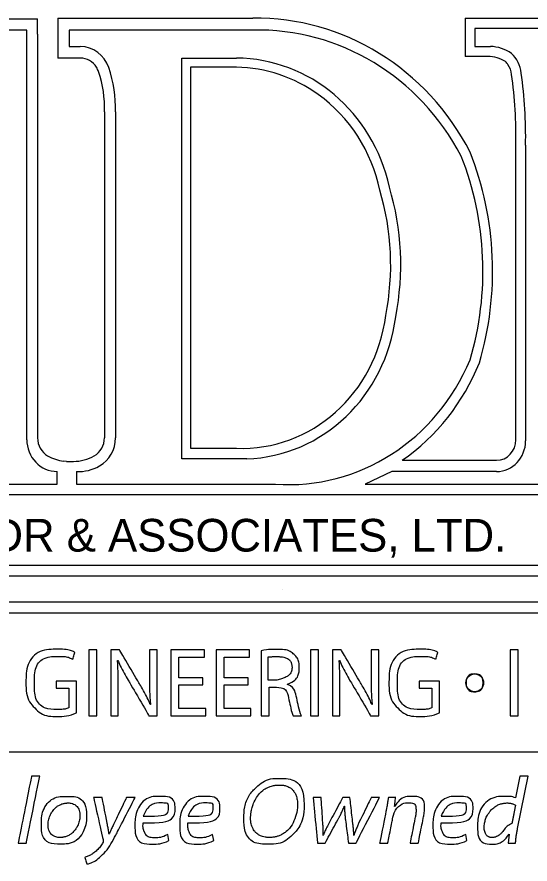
# Model space of a CAD drawing. Extents: x 0 to 170, y 0 to 110.
# Drawn here: x 162.45 to 164.962, y 16.154 to 20.302 of the extents above; entities that cross this region are included whole.
import ezdxf

# ---------------------------------------------------------------- set-up
doc = ezdxf.new("R2010")
doc.units = 0
doc.layers.add('SH_Data', color=7, linetype='Continuous')

msp = doc.modelspace()

# ---------------------------------------------------------------- linework, layer by layer
at = {"layer": 'SH_Data'}
for p, q in [((162.1704, 20.2922), (162.5504, 20.2922)), ((162.5504, 20.2173), (162.5504, 20.2922)), ((162.6498, 20.295), (162.6498, 20.1001)), ((162.6498, 20.295), (163.6048, 20.295)), ((164.6448, 20.295), (164.6448, 20.1073)), ((164.6448, 20.295), (165.5998, 20.295)), ((164.6448, 20.295), (164.6448, 20.1073)), ((164.6448, 20.295), (165.5998, 20.295)), ((162.5504, 20.2173), (162.5504, 18.2406)), ((162.721, 20.1001), (162.6498, 20.1001)), ((162.7599, 20.1001), (162.721, 20.1001)), ((164.716, 20.1073), (164.6448, 20.1073)), ((164.716, 20.1073), (164.6448, 20.1073)), ((164.7549, 20.1073), (164.716, 20.1073)), ((163.5243, 20.0551), (163.2988, 20.0551)), ((163.2988, 20.0551), (163.2988, 18.1896)), ((162.8783, 19.8365), (162.8783, 18.2406)), ((164.8926, 18.231), (164.8926, 19.6737)), ((163.2988, 18.1896), (163.3416, 18.1896)), ((163.3416, 18.1896), (163.5243, 18.1896)), ((162.6919, 18.1258), (162.6779, 18.1271)), ((162.6919, 18.1258), (162.6779, 18.1271)), ((162.6919, 18.1258), (162.7267, 18.1258)), ((164.3366, 18.131), (164.7976, 18.131)), ((161.0559, 17.6168), (166.4337, 17.6168)), ((163.75, 17.5), (163.75, 17.5)), ((167.2019, 17.3832), (160.3503, 17.3832)), ((163.7835, 17.1535), (163.7838, 17.1532)), ((163.6845, 17.0548), (163.6804, 17.0548)), ((163.7396, 17.0597), (163.7227, 17.0547)), ((163.7627, 17.068), (163.7396, 17.0597)), ((163.7746, 17.0336), (163.7746, 17.0351)), ((163.802, 16.88), (163.8424, 16.88)), ((160.2778, 16.7035), (167.2019, 16.7035)), ((163.6458, 16.5077), (163.6458, 16.5077)), ((164.8779, 16.4481), (164.8908, 16.4423)), ((163.1939, 16.2696), (163.1881, 16.2983)), ((163.4131, 16.2696), (163.4073, 16.2983)), ((164.6529, 16.2696), (164.647, 16.2983))]:
    msp.add_line(p, q, dxfattribs=at)
for points in [[(165.5998, 20.245), (164.6923, 20.245), (164.6923, 20.1573), (164.7678, 20.1573)], [(162.4982, 18.2317), (162.4982, 20.2372), (162.1988, 20.2372), (160.6706, 17.7601)], [(163.6048, 20.2372), (162.7049, 20.2372), (162.7049, 20.1566), (162.7599, 20.1566)], [(163.2569, 18.1379), (163.2569, 20.1001), (163.5243, 20.1001)], [(162.932, 19.8365), (162.932, 19.8341), (162.932, 18.2406)], [(164.9401, 19.6732), (164.9401, 18.226)], [(165.4659, 18.986), (166.5374, 17.5632), (161.0191, 17.5632)], [(163.5751, 18.1379), (163.2569, 18.1379)], [(164.3366, 18.131), (164.4469, 18.131)], [(162.0588, 18.0762), (161.2755, 18.0762), (161.2381, 18.0137), (162.646, 18.0137), (162.646, 18.0762)], [(162.7418, 18.0762), (162.7418, 18.0137), (163.7158, 18.0137)], [(164.7976, 18.076), (164.2849, 18.076), (164.1554, 18.0137), (166.1084, 18.0137), (166.0617, 18.076), (165.4111, 18.076)], [(166.2128, 17.9112), (166.1753, 17.9612), (161.2059, 17.9612), (161.0112, 17.636)], [(160.3301, 17.5029), (160.3301, 17.4382), (167.1497, 17.4382), (167.1497, 17.503)], [(163.6454, 17.1983), (163.6454, 16.88), (163.6845, 16.88), (163.6845, 17.0198), (163.7212, 17.0198)], [(163.7227, 17.0547), (163.7219, 17.0548), (163.7212, 17.0548)], [(164.9011, 16.3274), (164.9524, 16.585), (164.9122, 16.585), (164.8914, 16.4777)], [(164.8595, 16.3011), (164.8604, 16.3011), (164.8541, 16.2567), (164.8909, 16.2567)]]:
    msp.add_lwpolyline(points, dxfattribs=at)
msp.add_circle((164.6912, 17.0413), 0.0434, dxfattribs=at)
msp.add_arc((164.9095, 16.2677), 0.0927, 113.1884, 146.2819, dxfattribs=at)
for centre, major_axis, start_param, end_param in [((163.6216, 19.0409), (0, 1.2543), 5.209873, 6.297313), ((163.6301, 19.0406), (0, 1.1969), 5.218006, 6.305445), ((164.7609, 19.9483), (0, 0.2091), 5.696071, 6.248499), ((162.7599, 20.0001), (0, 0.1565), 5.060756, 6.283185), ((164.7755, 20.0082), (0, 0.1521), 4.832872, 5.561833), ((162.7599, 20.0001), (0, 0.1), 5.294753, 6.283185), ((163.5194, 19.286), (0, 0.8141), 4.938334, 6.276888), ((164.7609, 19.9483), (0, 0.1591), 5.717883, 6.322951), ((164.7755, 20.0082), (0, 0.1021), 5.34604, 5.529903), ((162.7599, 20.0001), (0, 0.1), 5.060756, 5.294753), ((162.3877, 19.8578), (0, 0.5168), 4.671123, 5.060756), ((162.3877, 19.8578), (0, 0.5733), 4.675194, 5.060756), ((163.5138, 19.2868), (0, 0.7683), 5.684676, 6.268828), ((164.7755, 20.0082), (0, 0.1021), 4.827568, 5.34604), ((164.7755, 20.0082), (0, 0.1021), 4.827568, 5.34604), ((162.8742, 19.7136), (0, 2.125), 4.693619, 4.857063), ((162.8742, 19.7136), (0, 2.125), 4.693619, 4.857063), ((162.8742, 19.7136), (0, 2.175), 4.693836, 4.856756), ((163.5138, 19.2868), (0, 0.7683), 4.930275, 5.684676), ((163.3375, 19.0583), (0, 1.467), 4.410917, 5.105556), ((163.3375, 19.0583), (0, 1.517), 4.410917, 5.105556), ((163.1229, 19.0881), (0, 1.2176), 4.507644, 5.016706), ((163.1301, 19.0885), (0, 1.2618), 4.509144, 5.018206), ((163.5497, 18.9384), (0, -0.7493), 6.247489, 7.723), ((163.5497, 18.9384), (0, -0.801), 0.033392, 1.439815), ((163.7786, 19.0349), (0, -1.0233), 6.218561, 7.439351), ((163.778, 19.0242), (0, -1.0693), 0.582172, 1.170799), ((162.6459, 18.2317), (0, -0.1555), 4.712389, 6.28383), ((162.6454, 18.2406), (0, -0.1), 4.712389, 5.785309), ((162.7833, 18.2406), (0, -0.1), 0.497877, 1.570796), ((162.7833, 18.2406), (0, -0.1566), 0.497877, 1.570796), ((164.7976, 18.231), (0, -0.1), 0, 1.570796), ((164.7976, 18.226), (0, -0.15), 0, 1.570796), ((162.7007, 18.3476), (0, -0.2218), 5.785308, 6.174936), ((162.728, 18.3476), (0, -0.2218), 6.276852, 6.781063), ((162.753, 18.2993), (0, -0.2234), 6.230381, 6.780961)]:
    msp.add_ellipse(centre, major_axis=major_axis, ratio=0.95, start_param=start_param, end_param=end_param, dxfattribs=at)
for points, degree in [([(162.742, 16.8944), (162.7245, 16.8877), (162.6899, 16.8767), (162.6491, 16.8767), (162.6033, 16.8767), (162.5657, 16.8891), (162.536, 16.9192), (162.51, 16.946), (162.4939, 16.9891), (162.4939, 17.0394), (162.4943, 17.1356), (162.5562, 17.2059), (162.6576, 17.2059), (162.6926, 17.2059), (162.72, 17.1978), (162.733, 17.1911), (162.733, 17.1911), (162.7236, 17.1571), (162.7236, 17.1571), (162.7074, 17.1648), (162.6872, 17.171), (162.6567, 17.171), (162.5832, 17.171), (162.5352, 17.1222), (162.5352, 17.0413), (162.5352, 16.9594), (162.5814, 16.9111), (162.6518, 16.9111), (162.6774, 16.9111), (162.6949, 16.9149), (162.7038, 16.9197), (162.7038, 16.9197), (162.7038, 17.0159), (162.7038, 17.0159), (162.7038, 17.0159), (162.6424, 17.0159), (162.6424, 17.0159), (162.6424, 17.0159), (162.6424, 17.0494), (162.6424, 17.0494), (162.6424, 17.0494), (162.742, 17.0494), (162.742, 17.0494), (162.742, 17.0494), (162.742, 16.8944), (162.742, 16.8944)], 3), ([(162.8406, 17.2026), (162.8406, 17.2026), (162.8406, 16.88), (162.8406, 16.88), (162.8406, 16.88), (162.8016, 16.88), (162.8016, 16.88), (162.8016, 16.88), (162.8016, 17.2026), (162.8016, 17.2026), (162.8016, 17.2026), (162.8406, 17.2026), (162.8406, 17.2026)], 3), ([(162.9088, 16.88), (162.9088, 16.88), (162.9088, 17.2026), (162.9088, 17.2026), (162.9088, 17.2026), (162.9515, 17.2026), (162.9515, 17.2026), (162.9515, 17.2026), (163.0484, 17.0394), (163.0484, 17.0394), (163.0708, 17.0016), (163.0883, 16.9676), (163.1026, 16.9346), (163.1026, 16.9346), (163.1035, 16.935), (163.1035, 16.935), (163.0999, 16.9781), (163.099, 17.0174), (163.099, 17.0676), (163.099, 17.0676), (163.099, 17.2026), (163.099, 17.2026), (163.099, 17.2026), (163.1358, 17.2026), (163.1358, 17.2026), (163.1358, 17.2026), (163.1358, 16.88), (163.1358, 16.88), (163.1358, 16.88), (163.0964, 16.88), (163.0964, 16.88), (163.0964, 16.88), (163.0003, 17.0437), (163.0003, 17.0437), (162.9793, 17.0796), (162.9591, 17.1164), (162.9438, 17.1514), (162.9438, 17.1514), (162.9425, 17.1509), (162.9425, 17.1509), (162.9447, 17.1102), (162.9456, 17.0714), (162.9456, 17.0178), (162.9456, 17.0178), (162.9456, 16.88), (162.9456, 16.88), (162.9456, 16.88), (162.9088, 16.88), (162.9088, 16.88)], 3), ([(163.3606, 17.0312), (163.3606, 17.0312), (163.243, 17.0312), (163.243, 17.0312), (163.243, 17.0312), (163.243, 16.9149), (163.243, 16.9149), (163.243, 16.9149), (163.374, 16.9149), (163.374, 16.9149), (163.374, 16.9149), (163.374, 16.88), (163.374, 16.88), (163.374, 16.88), (163.204, 16.88), (163.204, 16.88), (163.204, 16.88), (163.204, 17.2026), (163.204, 17.2026), (163.204, 17.2026), (163.3673, 17.2026), (163.3673, 17.2026), (163.3673, 17.2026), (163.3673, 17.1676), (163.3673, 17.1676), (163.3673, 17.1676), (163.243, 17.1676), (163.243, 17.1676), (163.243, 17.1676), (163.243, 17.0657), (163.243, 17.0657), (163.243, 17.0657), (163.3606, 17.0657), (163.3606, 17.0657), (163.3606, 17.0657), (163.3606, 17.0312), (163.3606, 17.0312)], 3), ([(163.5813, 17.0312), (163.5813, 17.0312), (163.4637, 17.0312), (163.4637, 17.0312), (163.4637, 17.0312), (163.4637, 16.9149), (163.4637, 16.9149), (163.4637, 16.9149), (163.5947, 16.9149), (163.5947, 16.9149), (163.5947, 16.9149), (163.5947, 16.88), (163.5947, 16.88), (163.5947, 16.88), (163.4247, 16.88), (163.4247, 16.88), (163.4247, 16.88), (163.4247, 17.2026), (163.4247, 17.2026), (163.4247, 17.2026), (163.588, 17.2026), (163.588, 17.2026), (163.588, 17.2026), (163.588, 17.1676), (163.588, 17.1676), (163.588, 17.1676), (163.4637, 17.1676), (163.4637, 17.1676), (163.4637, 17.1676), (163.4637, 17.0657), (163.4637, 17.0657), (163.4637, 17.0657), (163.5813, 17.0657), (163.5813, 17.0657), (163.5813, 17.0657), (163.5813, 17.0312), (163.5813, 17.0312)], 3), ([(163.7746, 17.0351), (163.8065, 17.0466), (163.8316, 17.0748), (163.8316, 17.1174), (163.8316, 17.1423), (163.8231, 17.1643), (163.8078, 17.1787), (163.789, 17.1968), (163.7621, 17.205), (163.7203, 17.205), (163.6934, 17.205), (163.6652, 17.2026), (163.6454, 17.1983)], 3), ([(163.9258, 17.2026), (163.9258, 17.2026), (163.9258, 16.88), (163.9258, 16.88), (163.9258, 16.88), (163.8868, 16.88), (163.8868, 16.88), (163.8868, 16.88), (163.8868, 17.2026), (163.8868, 17.2026), (163.8868, 17.2026), (163.9258, 17.2026), (163.9258, 17.2026)], 3), ([(163.994, 16.88), (163.994, 16.88), (163.994, 17.2026), (163.994, 17.2026), (163.994, 17.2026), (164.0366, 17.2026), (164.0366, 17.2026), (164.0366, 17.2026), (164.1335, 17.0394), (164.1335, 17.0394), (164.1559, 17.0016), (164.1734, 16.9676), (164.1878, 16.9346), (164.1878, 16.9346), (164.1887, 16.935), (164.1887, 16.935), (164.1851, 16.9781), (164.1842, 17.0174), (164.1842, 17.0676), (164.1842, 17.0676), (164.1842, 17.2026), (164.1842, 17.2026), (164.1842, 17.2026), (164.221, 17.2026), (164.221, 17.2026), (164.221, 17.2026), (164.221, 16.88), (164.221, 16.88), (164.221, 16.88), (164.1815, 16.88), (164.1815, 16.88), (164.1815, 16.88), (164.0855, 17.0437), (164.0855, 17.0437), (164.0644, 17.0796), (164.0442, 17.1164), (164.029, 17.1514), (164.029, 17.1514), (164.0276, 17.1509), (164.0276, 17.1509), (164.0299, 17.1102), (164.0308, 17.0714), (164.0308, 17.0178), (164.0308, 17.0178), (164.0308, 16.88), (164.0308, 16.88), (164.0308, 16.88), (163.994, 16.88), (163.994, 16.88)], 3), ([(164.5193, 16.8944), (164.5018, 16.8877), (164.4673, 16.8767), (164.4264, 16.8767), (164.3807, 16.8767), (164.343, 16.8891), (164.3134, 16.9192), (164.2874, 16.946), (164.2712, 16.9891), (164.2712, 17.0394), (164.2717, 17.1356), (164.3336, 17.2059), (164.435, 17.2059), (164.4699, 17.2059), (164.4973, 17.1978), (164.5103, 17.1911), (164.5103, 17.1911), (164.5009, 17.1571), (164.5009, 17.1571), (164.4847, 17.1648), (164.4646, 17.171), (164.434, 17.171), (164.3605, 17.171), (164.3125, 17.1222), (164.3125, 17.0413), (164.3125, 16.9594), (164.3587, 16.9111), (164.4291, 16.9111), (164.4547, 16.9111), (164.4722, 16.9149), (164.4812, 16.9197), (164.4812, 16.9197), (164.4812, 17.0159), (164.4812, 17.0159), (164.4812, 17.0159), (164.4197, 17.0159), (164.4197, 17.0159), (164.4197, 17.0159), (164.4197, 17.0494), (164.4197, 17.0494), (164.4197, 17.0494), (164.5193, 17.0494), (164.5193, 17.0494), (164.5193, 17.0494), (164.5193, 16.8944), (164.5193, 16.8944)], 3), ([(164.9033, 17.2026), (164.9033, 17.2026), (164.9033, 16.88), (164.9033, 16.88), (164.9033, 16.88), (164.8642, 16.88), (164.8642, 16.88), (164.8642, 16.88), (164.8642, 17.2026), (164.8642, 17.2026), (164.8642, 17.2026), (164.9033, 17.2026), (164.9033, 17.2026)], 3), ([(163.6804, 17.1681), (163.6909, 17.1691), (163.7025, 17.1697), (163.7152, 17.1699), (163.7174, 17.17), (163.7195, 17.17), (163.7209, 17.17), (163.7218, 17.17), (163.7258, 17.1699), (163.7289, 17.1699), (163.7378, 17.1694), (163.7431, 17.1689), (163.7574, 17.1669), (163.7646, 17.1648), (163.7757, 17.1599), (163.7797, 17.1571), (163.7835, 17.1535)], 3), ([(163.6804, 17.0548), (163.6804, 17.0987), (163.6804, 17.1409), (163.6804, 17.1681)], 2), ([(163.7838, 17.1532), (163.7861, 17.151), (163.7883, 17.1483), (163.792, 17.1416), (163.7936, 17.1376), (163.7959, 17.1285), (163.7965, 17.1234), (163.7966, 17.1164), (163.7966, 17.1149), (163.7964, 17.1122), (163.7963, 17.1109), (163.7958, 17.1071), (163.7954, 17.1047), (163.7926, 17.0935), (163.7887, 17.0867), (163.7778, 17.0754), (163.7708, 17.0709), (163.7627, 17.068)], 3), ([(163.7212, 17.0548), (163.7211, 17.0548), (163.6846, 17.0548), (163.6845, 17.0548)], 2), ([(164.7328, 17.0413), (164.7328, 17.0173), (164.7142, 16.9979), (164.6912, 16.9979), (164.6682, 16.9979), (164.6495, 17.0173), (164.6495, 17.0413), (164.6495, 17.0652), (164.6682, 17.0846), (164.6912, 17.0846), (164.7142, 17.0846), (164.7328, 17.0652), (164.7328, 17.0413)], 3), ([(163.7212, 17.0198), (163.7567, 17.0183), (163.7728, 17.0016), (163.7818, 16.9571), (163.7903, 16.9169), (163.797, 16.8896), (163.802, 16.88)], 3), ([(163.8424, 16.88), (163.8361, 16.8924), (163.8289, 16.9236), (163.819, 16.9685), (163.8119, 17.002), (163.798, 17.025), (163.7746, 17.0336)], 3), ([(162.4559, 16.2567), (162.4559, 16.2567), (162.5212, 16.585), (162.5212, 16.585), (162.5212, 16.585), (162.5614, 16.585), (162.5614, 16.585), (162.5614, 16.585), (162.4956, 16.2567), (162.4956, 16.2567), (162.4956, 16.2567), (162.4559, 16.2567), (162.4559, 16.2567)], 3), ([(163.8558, 16.4458), (163.8558, 16.5124), (163.8205, 16.5735), (163.7329, 16.5735), (163.6918, 16.5735), (163.6512, 16.5573), (163.6236, 16.5314), (163.5839, 16.4939), (163.5612, 16.4333), (163.5612, 16.3783), (163.5612, 16.3122), (163.6008, 16.2516), (163.685, 16.2516), (163.73, 16.2516), (163.7678, 16.2678), (163.7968, 16.2951), (163.8355, 16.3321), (163.8558, 16.3917), (163.8558, 16.4458)], 3), ([(163.7745, 16.3187), (163.7657, 16.3104), (163.756, 16.3036), (163.7351, 16.2928), (163.7237, 16.2888), (163.7051, 16.2853), (163.6986, 16.2846), (163.6901, 16.2842), (163.688, 16.2841), (163.6857, 16.2841), (163.6852, 16.2841), (163.685, 16.2841), (163.6847, 16.2841), (163.6841, 16.2841), (163.6821, 16.2841), (163.6802, 16.2842), (163.6725, 16.2845), (163.6669, 16.2852), (163.6512, 16.2883), (163.6425, 16.2916), (163.6276, 16.3002), (163.6213, 16.3054), (163.6106, 16.3177), (163.6062, 16.3248), (163.5991, 16.3407), (163.5966, 16.3495), (163.5944, 16.3636), (163.5939, 16.3684), (163.5937, 16.3746), (163.5937, 16.3758), (163.5936, 16.3777), (163.5936, 16.3783), (163.5937, 16.3794), (163.5937, 16.3821), (163.5938, 16.3848), (163.5943, 16.3958), (163.5954, 16.4049), (163.6008, 16.4319), (163.6069, 16.4499), (163.6236, 16.4822), (163.634, 16.4965), (163.6458, 16.5077)], 3), ([(163.6458, 16.5077), (163.6563, 16.5175), (163.6698, 16.526), (163.6925, 16.5348), (163.7004, 16.5371), (163.7125, 16.5394), (163.7166, 16.54), (163.7227, 16.5406), (163.7258, 16.5408), (163.7294, 16.5409), (163.7312, 16.5409), (163.7321, 16.541), (163.7325, 16.541), (163.7327, 16.541), (163.7328, 16.541), (163.7328, 16.541), (163.7511, 16.541), (163.7651, 16.5378), (163.7873, 16.5283), (163.7956, 16.5218), (163.8091, 16.5056), (163.8143, 16.4958), (163.8215, 16.4727), (163.8233, 16.4596), (163.8233, 16.4458)], 3), ([(162.7908, 16.3922), (162.7908, 16.4398), (162.7627, 16.4856), (162.6993, 16.4856), (162.6234, 16.4856), (162.5696, 16.4172), (162.5696, 16.3436), (162.5696, 16.2932), (162.6025, 16.2516), (162.6611, 16.2516), (162.7395, 16.2516), (162.7908, 16.3233), (162.7908, 16.3922)], 3), ([(162.8667, 16.4805), (162.8667, 16.4805), (162.89, 16.3603), (162.89, 16.3603), (162.8953, 16.3344), (162.8982, 16.3177), (162.9006, 16.3011), (162.9006, 16.3011), (162.9016, 16.3011), (162.9016, 16.3011), (162.9079, 16.3154), (162.9146, 16.3312), (162.9268, 16.3556), (162.9268, 16.3556), (162.9863, 16.4805), (162.9863, 16.4805), (162.9863, 16.4805), (163.0289, 16.4805), (163.0289, 16.4805), (163.0289, 16.4805), (162.9413, 16.3103), (162.9413, 16.3103), (162.9161, 16.2618), (162.8924, 16.2225), (162.8605, 16.1929), (162.8343, 16.1675), (162.8058, 16.1568), (162.7922, 16.154), (162.7922, 16.154), (162.7825, 16.1869), (162.7825, 16.1869), (162.7927, 16.1906), (162.8096, 16.1966), (162.8256, 16.2086), (162.8411, 16.2202), (162.858, 16.2382), (162.8706, 16.2599), (162.8726, 16.2636), (162.8726, 16.2664), (162.8721, 16.2701), (162.8721, 16.2701), (162.8251, 16.4805), (162.8251, 16.4805), (162.8251, 16.4805), (162.8667, 16.4805), (162.8667, 16.4805)], 3), ([(163.068, 16.3552), (163.1547, 16.3538), (163.2239, 16.3695), (163.2239, 16.4283), (163.2239, 16.4602), (163.1997, 16.4856), (163.1551, 16.4856), (163.0797, 16.4856), (163.0274, 16.4093), (163.0274, 16.3418), (163.0274, 16.2923), (163.0545, 16.2516), (163.1164, 16.2516), (163.1479, 16.2516), (163.1764, 16.2599), (163.1939, 16.2696)], 3), ([(163.2872, 16.3552), (163.3739, 16.3538), (163.4431, 16.3695), (163.4431, 16.4283), (163.4431, 16.4602), (163.4189, 16.4856), (163.3743, 16.4856), (163.2989, 16.4856), (163.2466, 16.4093), (163.2466, 16.3418), (163.2466, 16.2923), (163.2737, 16.2516), (163.3356, 16.2516), (163.3671, 16.2516), (163.3957, 16.2599), (163.4131, 16.2696)], 3), ([(163.9391, 16.4805), (163.9391, 16.4805), (163.9473, 16.3547), (163.9473, 16.3547), (163.9492, 16.327), (163.9488, 16.3126), (163.9483, 16.2946), (163.9483, 16.2946), (163.9497, 16.2946), (163.9497, 16.2946), (163.955, 16.3089), (163.9638, 16.3284), (163.9754, 16.3506), (163.9754, 16.3506), (164.0451, 16.4805), (164.0451, 16.4805), (164.0451, 16.4805), (164.0799, 16.4805), (164.0799, 16.4805), (164.0799, 16.4805), (164.0944, 16.3529), (164.0944, 16.3529), (164.0968, 16.3284), (164.0988, 16.3094), (164.0983, 16.2946), (164.0983, 16.2946), (164.0992, 16.2946), (164.0992, 16.2946), (164.1055, 16.3126), (164.1123, 16.3298), (164.1215, 16.351), (164.1215, 16.351), (164.1849, 16.4805), (164.1849, 16.4805), (164.1849, 16.4805), (164.2255, 16.4805), (164.2255, 16.4805), (164.2255, 16.4805), (164.1099, 16.2567), (164.1099, 16.2567), (164.1099, 16.2567), (164.0726, 16.2567), (164.0726, 16.2567), (164.0726, 16.2567), (164.0572, 16.3783), (164.0572, 16.3783), (164.0547, 16.3991), (164.0538, 16.4181), (164.0538, 16.4375), (164.0538, 16.4375), (164.0528, 16.4375), (164.0528, 16.4375), (164.0431, 16.4162), (164.0363, 16.3991), (164.0257, 16.3792), (164.0257, 16.3792), (163.9584, 16.2567), (163.9584, 16.2567), (163.9584, 16.2567), (163.9212, 16.2567), (163.9212, 16.2567), (163.9212, 16.2567), (163.8994, 16.4805), (163.8994, 16.4805), (163.8994, 16.4805), (163.9391, 16.4805), (163.9391, 16.4805)], 3), ([(164.2255, 16.2567), (164.2255, 16.2567), (164.257, 16.4153), (164.257, 16.4153), (164.2623, 16.4403), (164.2652, 16.462), (164.2681, 16.4805), (164.2681, 16.4805), (164.304, 16.4805), (164.304, 16.4805), (164.304, 16.4805), (164.2981, 16.4366), (164.2981, 16.4366), (164.2981, 16.4366), (164.2991, 16.4366), (164.2991, 16.4366), (164.3199, 16.468), (164.3514, 16.4856), (164.3857, 16.4856), (164.4138, 16.4856), (164.4452, 16.4703), (164.4452, 16.4232), (164.4452, 16.4135), (164.4433, 16.3991), (164.4409, 16.3871), (164.4409, 16.3871), (164.4148, 16.2567), (164.4148, 16.2567), (164.4148, 16.2567), (164.3746, 16.2567), (164.3746, 16.2567), (164.3746, 16.2567), (164.4002, 16.3857), (164.4002, 16.3857), (164.4022, 16.3945), (164.4036, 16.4051), (164.4036, 16.4144), (164.4036, 16.437), (164.3944, 16.4537), (164.3668, 16.4537), (164.3383, 16.4537), (164.2977, 16.4209), (164.287, 16.3654), (164.287, 16.3654), (164.2657, 16.2567), (164.2657, 16.2567), (164.2657, 16.2567), (164.2255, 16.2567), (164.2255, 16.2567)], 3), ([(164.527, 16.3552), (164.6136, 16.3538), (164.6828, 16.3695), (164.6828, 16.4283), (164.6828, 16.4602), (164.6587, 16.4856), (164.6141, 16.4856), (164.5386, 16.4856), (164.4864, 16.4093), (164.4864, 16.3418), (164.4864, 16.2923), (164.5135, 16.2516), (164.5754, 16.2516), (164.6069, 16.2516), (164.6354, 16.2599), (164.6529, 16.2696)], 3), ([(164.8914, 16.4777), (164.8812, 16.4824), (164.8648, 16.4856), (164.8498, 16.4856), (164.767, 16.4856), (164.7051, 16.4125), (164.7051, 16.333), (164.7051, 16.2872), (164.7298, 16.2516), (164.7753, 16.2516), (164.8087, 16.2516), (164.8382, 16.2692), (164.8595, 16.3011)], 3), ([(162.6021, 16.3436), (162.6021, 16.3581), (162.6048, 16.3723), (162.6146, 16.3987), (162.6217, 16.4108), (162.6393, 16.4309), (162.6496, 16.4389), (162.6668, 16.4472), (162.6729, 16.4494), (162.6824, 16.4516), (162.6857, 16.4521), (162.6907, 16.4527), (162.6932, 16.4529), (162.6963, 16.453), (162.6976, 16.4531), (162.6984, 16.4531), (162.699, 16.4531), (162.7113, 16.4531), (162.7203, 16.451), (162.7344, 16.4448), (162.7397, 16.4407), (162.7486, 16.4304), (162.7521, 16.4241), (162.757, 16.4093), (162.7583, 16.4009), (162.7583, 16.3922)], 3), ([(163.0682, 16.3879), (163.0821, 16.4251), (163.1131, 16.4531), (163.1551, 16.4531), (163.1857, 16.4531), (163.1914, 16.4472), (163.1914, 16.4283), (163.1914, 16.3983), (163.1578, 16.3881), (163.0682, 16.3879)], 3), ([(163.2874, 16.3879), (163.3013, 16.4251), (163.3323, 16.4531), (163.3743, 16.4531), (163.4049, 16.4531), (163.4106, 16.4472), (163.4106, 16.4283), (163.4106, 16.3983), (163.3771, 16.3881), (163.2874, 16.3879)], 3), ([(163.8233, 16.4458), (163.8233, 16.4229), (163.8189, 16.398), (163.802, 16.3531), (163.7895, 16.3331), (163.7745, 16.3187)], 3), ([(164.5271, 16.3879), (164.5411, 16.4251), (164.572, 16.4531), (164.6141, 16.4531), (164.6447, 16.4531), (164.6503, 16.4472), (164.6503, 16.4283), (164.6503, 16.3983), (164.6168, 16.3881), (164.5271, 16.3879)], 3), ([(164.8324, 16.3191), (164.8271, 16.3112), (164.8214, 16.3047), (164.8096, 16.2946), (164.8036, 16.291), (164.7913, 16.2859), (164.7849, 16.2845), (164.7763, 16.2841), (164.7745, 16.2841), (164.7712, 16.2842), (164.7696, 16.2844), (164.7652, 16.2851), (164.7627, 16.2858), (164.756, 16.2884), (164.7526, 16.2908), (164.7464, 16.2978), (164.7435, 16.3024), (164.7393, 16.3145), (164.7379, 16.3218), (164.7374, 16.3386), (164.7381, 16.3467), (164.7424, 16.3708), (164.7485, 16.3861), (164.7656, 16.4133), (164.7767, 16.425), (164.8021, 16.4428), (164.8164, 16.4489), (164.836, 16.4523), (164.8399, 16.4527), (164.8481, 16.4532), (164.8523, 16.4532), (164.8611, 16.4524), (164.8657, 16.4517), (164.8734, 16.4499), (164.8766, 16.4487), (164.8779, 16.4481)], 3), ([(164.8908, 16.4423), (164.8837, 16.4066), (164.877, 16.373), (164.873, 16.3529)], 2), ([(162.7583, 16.3922), (162.7583, 16.379), (162.7558, 16.3653), (162.7463, 16.3394), (162.7393, 16.3273), (162.7219, 16.307), (162.7116, 16.2987), (162.6943, 16.2902), (162.6882, 16.288), (162.6785, 16.2857), (162.6752, 16.2851), (162.67, 16.2845), (162.6674, 16.2843), (162.6643, 16.2842), (162.6627, 16.2841), (162.662, 16.2841), (162.6615, 16.2841), (162.6613, 16.2841), (162.6503, 16.2841), (162.6416, 16.286), (162.6274, 16.2919), (162.6218, 16.2959), (162.6125, 16.3059), (162.6088, 16.3119), (162.6036, 16.3263), (162.6021, 16.3346), (162.6021, 16.3436)], 3), ([(163.1881, 16.2983), (163.1735, 16.2909), (163.1527, 16.2826), (163.1251, 16.2826), (163.1009, 16.2826), (163.0821, 16.2928), (163.0729, 16.3126), (163.0675, 16.3247), (163.0661, 16.3455), (163.068, 16.3552)], 3), ([(163.4073, 16.2983), (163.3927, 16.2909), (163.3719, 16.2826), (163.3444, 16.2826), (163.3201, 16.2826), (163.3013, 16.2928), (163.2921, 16.3126), (163.2868, 16.3247), (163.2853, 16.3455), (163.2872, 16.3552)], 3), ([(164.647, 16.2983), (164.6325, 16.2909), (164.6117, 16.2826), (164.5841, 16.2826), (164.5599, 16.2826), (164.5411, 16.2928), (164.5319, 16.3126), (164.5265, 16.3247), (164.5251, 16.3455), (164.527, 16.3552)], 3), ([(164.8909, 16.2567), (164.8924, 16.2784), (164.8962, 16.3043), (164.9011, 16.3274)], 2)]:
    msp.add_open_spline(points, degree=degree, dxfattribs=at)

# ---------------------------------------------------------------- texts
msp.add_text('ADR & ASSOCIATES, LTD.', height=0.16, dxfattribs=at).set_placement((162.1823, 17.684))

doc.saveas('drawing.dxf')
